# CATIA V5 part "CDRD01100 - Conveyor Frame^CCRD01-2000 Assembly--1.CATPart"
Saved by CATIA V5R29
Part number: CDRD01100 - Conveyor Frame^CCRD01-2000 Assembly--1
Definition: design
Source: Unknown
Bounding box of the stored display mesh (mm): x -4 to 54, y -4 to 134, z 0 to 2000
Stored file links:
  C:\가치같이\SmartFactory_BoxErectorConveyor\CDRD01100 - Conveyor Frame^CCRD01-2000 Assembly--1.CATPart
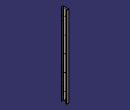
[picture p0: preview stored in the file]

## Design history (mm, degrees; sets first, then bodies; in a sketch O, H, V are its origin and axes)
Body1 "Cut-Extrude5" (main body)
  Solid1: solid without history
